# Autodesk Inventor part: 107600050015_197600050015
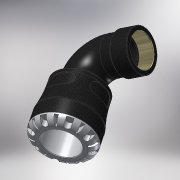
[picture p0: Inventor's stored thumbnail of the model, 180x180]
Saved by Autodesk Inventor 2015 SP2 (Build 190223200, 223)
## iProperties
Created: 2016-12
Part Number: 107600050015_197600050015
Material: PVC-Piping
Description: PLASSON 90° ELBOW WITH FEMALE INTEGRAL BRASS 50X1.1/2" SERIES 1
Document SubType Name: Modeling
Designer: KIM
Mass: 664.223 g
Surface Area: 733.008 cm^2
Volume: 474.445 cm^3
Density: 1.4 g/cm^3
Appearance: Black Cast
Author: KIM
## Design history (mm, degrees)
derived "1076.ipt"
feature "Solid1::1076.ipt"
tag "TaggingFeature1"
body "Solid1"
other parameters: "d1" = 33.18, "d3" = 62.5, "d4" = 85, "d8" = 74.8, "d13" = 9, "d14" = 9, "d15" = 0, "d17" = 360 deg, "d19" = 8 deg, "d20" = 1, "d21" = 1, "d22" = 8 deg, "d24" = 0, "d26" = 360 deg, "d33" = 8.5, "d51" = 0.85, "d54" = 17.5, "d55" = 11, "d57" = 17.64, "d58" = 0, "d74" = 0, "d78" = 79, "d82" = 1, "d115" = 360 deg, "d207" = 90 deg, "d228" = 14.875, "d248" = 4.74, "d270" = 122, "d279" = 73, "d281" = 6.72675, "d294" = 44.845, "d295" = 21, "d296" = 23.1, "d297" = 40.3605, "d299" = 52.46865, "d300" = 40.3605, "d301" = 0, "d302" = 0, "d306" = 2.91492, "d309" = 79.79, "d310" = 11.16568, "d312" = 15 deg, "d313" = 0.68, "d314" = 9.006, "d315" = 0.425, "E_" = 85, "l_" = 79, "A_" = 122, "A_1" = 73, "l_2" = 21, "Rp_" = 44.845, "d9" = 11.25, "d11" = 85, "d12" = 62.5, "d298" = 58.2985
